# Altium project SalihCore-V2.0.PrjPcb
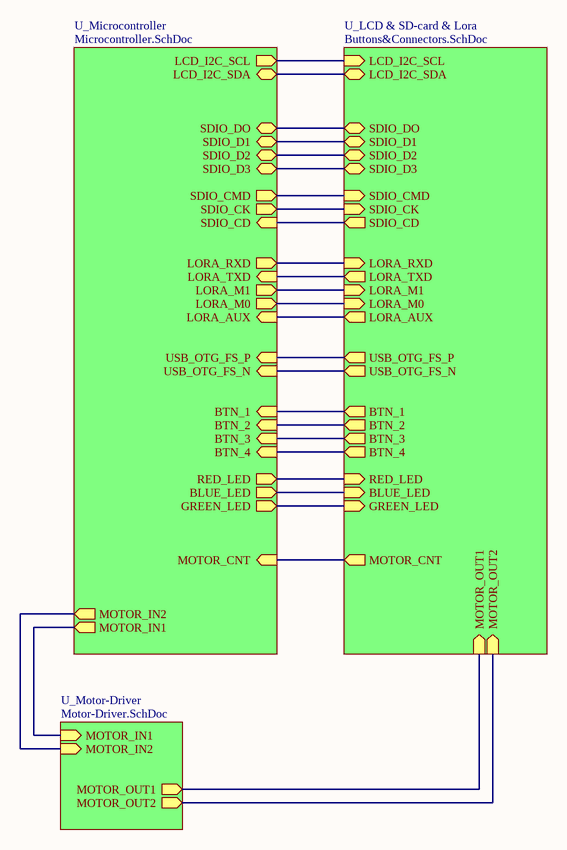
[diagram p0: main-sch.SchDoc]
6 sheets, 107 parts. Net scope: hierarchical (ports join the sheet entries above them; power ports are global).
Board file: SalihCore-V2.0-PCB.PcbDoc
Sheets:
  main-sch.SchDoc
    U_Microcontroller = Microcontroller.SchDoc
    U_LCD & SD-card & Lora = Buttons&Connectors.SchDoc
    U_Motor-Driver = Motor-Driver.SchDoc
  SMPS.SchDoc
  TP4056.SchDoc

## Sheet main-sch.SchDoc
size A; SheetNumber: 1; SheetTotal: 6

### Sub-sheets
U_LCD & SD-card & Lora = Buttons&Connectors.SchDoc: LCD_I2C_SCL (in), LCD_I2C_SDA (bidir), SDIO_DO (bidir), SDIO_D1 (bidir), SDIO_D2 (bidir), SDIO_D3 (bidir), SDIO_CMD (in), SDIO_CK (in), SDIO_CD (out), LORA_RXD (in), LORA_TXD (out), LORA_M1 (in), LORA_M0 (in), LORA_AUX (out), BTN_1 (out), BTN_2 (out), BTN_3 (out), BTN_4 (out), MOTOR_OUT1 (in), MOTOR_OUT2 (in), MOTOR_CNT (out), RED_LED (in), BLUE_LED (in), GREEN_LED (in), USB_OTG_FS_P (out), USB_OTG_FS_N (out)
U_Microcontroller = Microcontroller.SchDoc: SDIO_DO (bidir), SDIO_D1 (bidir), SDIO_D2 (bidir), SDIO_D3 (bidir), SDIO_CK (out), SDIO_CMD (out), LCD_I2C_SCL (out), LCD_I2C_SDA (bidir), SDIO_CD (in), LORA_RXD (out), LORA_TXD (in), LORA_M1 (out), LORA_M0 (out), LORA_AUX (in), MOTOR_IN1 (out), MOTOR_IN2 (out), BTN_1 (in), BTN_2 (in), BTN_3 (in), BTN_4 (in), MOTOR_CNT (in), RED_LED (out), BLUE_LED (out), GREEN_LED (out), USB_OTG_FS_P (in), USB_OTG_FS_N (in)
U_Motor-Driver = Motor-Driver.SchDoc: MOTOR_IN1 (in), MOTOR_IN2 (in), MOTOR_OUT1 (out), MOTOR_OUT2 (out)

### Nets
BLUE_LED: sheet U_Microcontroller/BLUE_LED, sheet U_LCD & SD-card & Lora/BLUE_LED
BTN_1: sheet U_Microcontroller/BTN_1, sheet U_LCD & SD-card & Lora/BTN_1
BTN_2: sheet U_Microcontroller/BTN_2, sheet U_LCD & SD-card & Lora/BTN_2
BTN_3: sheet U_Microcontroller/BTN_3, sheet U_LCD & SD-card & Lora/BTN_3
BTN_4: sheet U_Microcontroller/BTN_4, sheet U_LCD & SD-card & Lora/BTN_4
GREEN_LED: sheet U_Microcontroller/GREEN_LED, sheet U_LCD & SD-card & Lora/GREEN_LED
LCD_I2C_SCL: sheet U_Microcontroller/LCD_I2C_SCL, sheet U_LCD & SD-card & Lora/LCD_I2C_SCL
LCD_I2C_SDA: sheet U_Microcontroller/LCD_I2C_SDA, sheet U_LCD & SD-card & Lora/LCD_I2C_SDA
LORA_AUX: sheet U_Microcontroller/LORA_AUX, sheet U_LCD & SD-card & Lora/LORA_AUX
LORA_M0: sheet U_Microcontroller/LORA_M0, sheet U_LCD & SD-card & Lora/LORA_M0
LORA_M1: sheet U_Microcontroller/LORA_M1, sheet U_LCD & SD-card & Lora/LORA_M1
LORA_RXD: sheet U_Microcontroller/LORA_RXD, sheet U_LCD & SD-card & Lora/LORA_RXD
LORA_TXD: sheet U_Microcontroller/LORA_TXD, sheet U_LCD & SD-card & Lora/LORA_TXD
MOTOR_CNT: sheet U_Microcontroller/MOTOR_CNT, sheet U_LCD & SD-card & Lora/MOTOR_CNT
MOTOR_IN1: sheet U_Microcontroller/MOTOR_IN1, sheet U_Motor-Driver/MOTOR_IN1
MOTOR_IN2: sheet U_Microcontroller/MOTOR_IN2, sheet U_Motor-Driver/MOTOR_IN2
MOTOR_OUT1: sheet U_LCD & SD-card & Lora/MOTOR_OUT1, sheet U_Motor-Driver/MOTOR_OUT1
MOTOR_OUT2: sheet U_LCD & SD-card & Lora/MOTOR_OUT2, sheet U_Motor-Driver/MOTOR_OUT2
RED_LED: sheet U_Microcontroller/RED_LED, sheet U_LCD & SD-card & Lora/RED_LED
SDIO_CD: sheet U_Microcontroller/SDIO_CD, sheet U_LCD & SD-card & Lora/SDIO_CD
SDIO_CK: sheet U_Microcontroller/SDIO_CK, sheet U_LCD & SD-card & Lora/SDIO_CK
SDIO_CMD: sheet U_Microcontroller/SDIO_CMD, sheet U_LCD & SD-card & Lora/SDIO_CMD
SDIO_D1: sheet U_Microcontroller/SDIO_D1, sheet U_LCD & SD-card & Lora/SDIO_D1
SDIO_D2: sheet U_Microcontroller/SDIO_D2, sheet U_LCD & SD-card & Lora/SDIO_D2
SDIO_D3: sheet U_Microcontroller/SDIO_D3, sheet U_LCD & SD-card & Lora/SDIO_D3
SDIO_DO: sheet U_Microcontroller/SDIO_DO, sheet U_LCD & SD-card & Lora/SDIO_DO
USB_OTG_FS_N: sheet U_Microcontroller/USB_OTG_FS_N, sheet U_LCD & SD-card & Lora/USB_OTG_FS_N
USB_OTG_FS_P: sheet U_Microcontroller/USB_OTG_FS_P, sheet U_LCD & SD-card & Lora/USB_OTG_FS_P

## Sheet Microcontroller.SchDoc
size C; SheetNumber: 2; SheetTotal: 6
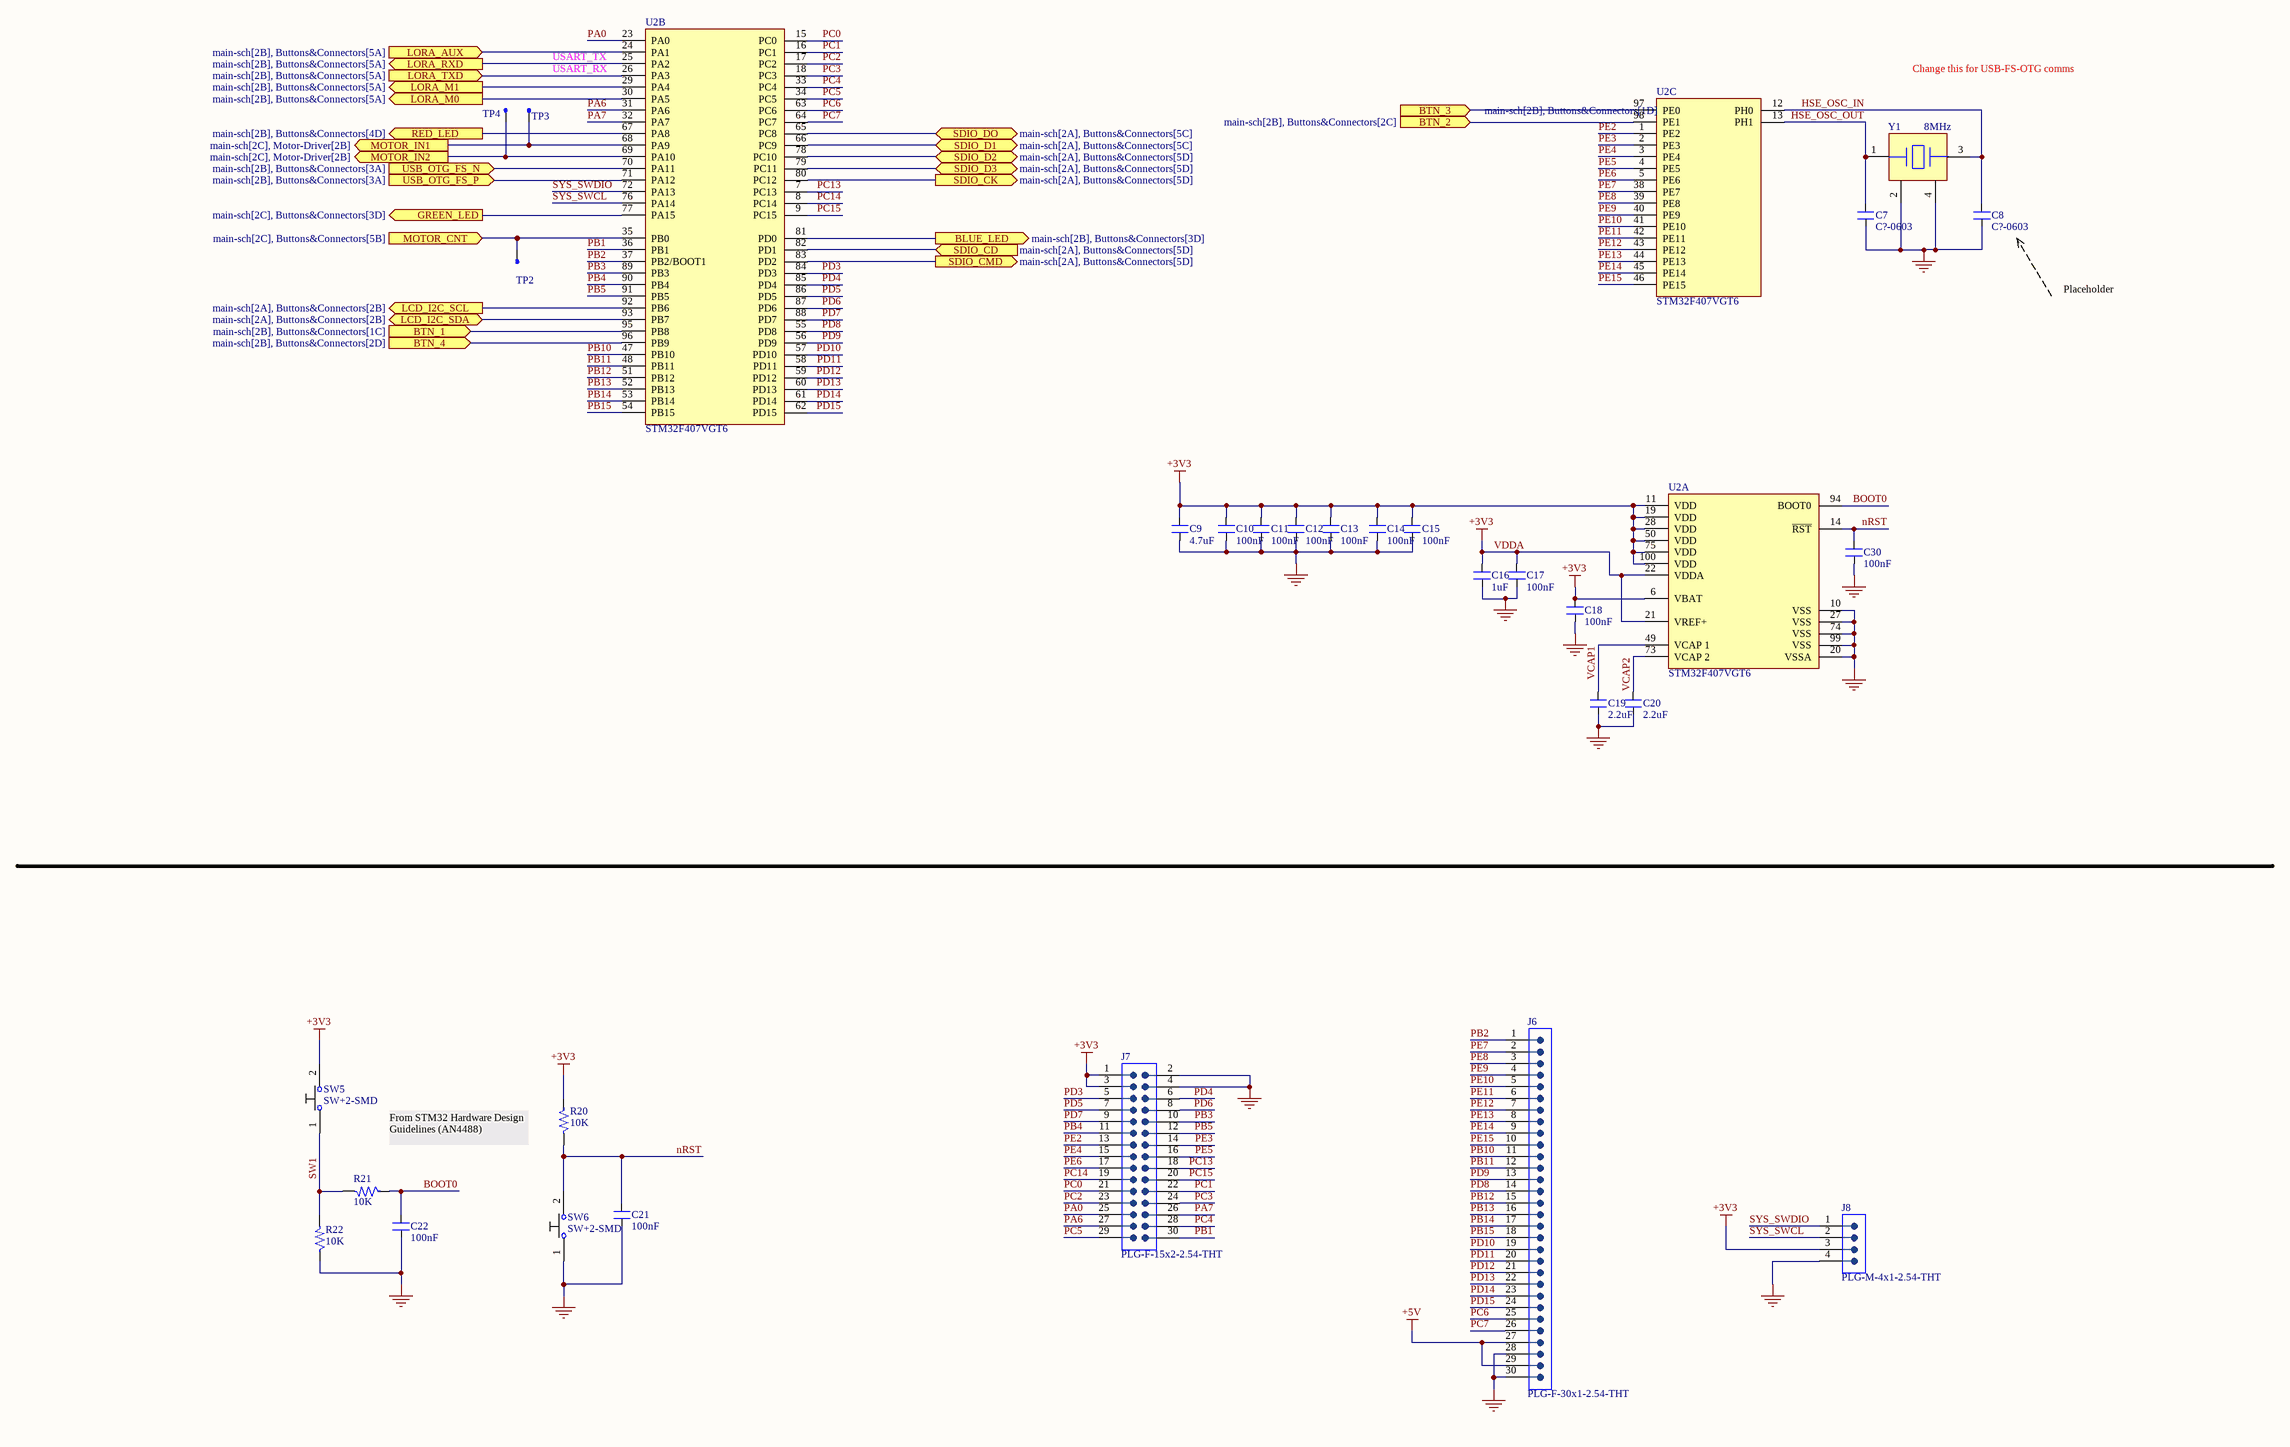
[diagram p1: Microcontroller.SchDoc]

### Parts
(Parts that share a designator on the sheet are numbered #1, #2 ... from top to bottom, then left to right.)
C7  C?-0603  [CAP-0603]
C8  C?-0603  [CAP-0603]
C9  4.7uF  [CAP-0603]
C10  100nF  [CAP-0603]
C11  100nF  [CAP-0603]
C12  100nF  [CAP-0603]
C13  100nF  [CAP-0603]
C14  100nF  [CAP-0603]
C15  100nF  [CAP-0603]
C16  1uF  [CAP-0603]
C17  100nF  [CAP-0603]
C18  100nF  [CAP-0603]
C19  2.2uF  [CAP-0603]
C20  2.2uF  [CAP-0603]
C21  100nF  [CAP-0603]
C22  100nF  [CAP-0603]
C30  100nF  [CAP-0603]
J6#1  PLG-F-30x1-2.54-THT  [PLG-F-30x1-2.54-THT]
J7  PLG-F-15x2-2.54-THT  [PLG-F-15x2-2.54-THT]
J8  PLG-M-4x1-2.54-THT  [PLG-M-4x1-2.54-THT]
R20  10K  [RES-0603]
R21  10K  [RES-0603]
R22  10K  [RES-0603]
SW5  SW+2-SMD  [SW+2-SMD]
SW6  SW+2-SMD  [SW+2-SMD]
TP2  Test-Point  [Test Point]  (value not drawn)
TP3  Test-Point  [Test Point]  (value not drawn)
TP4  Test-Point  [Test Point]  (value not drawn)
U2  STM32F407VGT6  [LQFP-100-14x14]  (parts A,B,C of 3)
Y1  8MHz  [XTAL-TX32258M4LBDE2T-HM]

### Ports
BLUE_LED (out, see main-sch[2B], Buttons&Connectors[3D]), BTN_1 (in, see main-sch[2B], Buttons&Connectors[1C]), BTN_2 (in, see main-sch[2B], Buttons&Connectors[2C]), BTN_3 (in, see main-sch[2B], Buttons&Connectors[1D]), BTN_4 (in, see main-sch[2B], Buttons&Connectors[2D]), GREEN_LED (out, see main-sch[2C], Buttons&Connectors[3D]), LCD_I2C_SCL (out, see main-sch[2A], Buttons&Connectors[2B]), LCD_I2C_SDA (bidir, see main-sch[2A], Buttons&Connectors[2B]), LORA_AUX (in, see main-sch[2B], Buttons&Connectors[5A]), LORA_M0 (out, see main-sch[2B], Buttons&Connectors[5A]), LORA_M1 (out, see main-sch[2B], Buttons&Connectors[5A]), LORA_RXD (out, see main-sch[2B], Buttons&Connectors[5A]), LORA_TXD (in, see main-sch[2B], Buttons&Connectors[5A]), MOTOR_CNT (in, see main-sch[2C], Buttons&Connectors[5B]), MOTOR_IN1 (out, see main-sch[2C], Motor-Driver[2B]), MOTOR_IN2 (out, see main-sch[2C], Motor-Driver[2B]), RED_LED (out, see main-sch[2B], Buttons&Connectors[4D]), SDIO_CD (in, see main-sch[2A], Buttons&Connectors[5D]), SDIO_CK (out, see main-sch[2A], Buttons&Connectors[5D]), SDIO_CMD (out, see main-sch[2A], Buttons&Connectors[5D]), SDIO_D1 (bidir, see main-sch[2A], Buttons&Connectors[5C]), SDIO_D2 (bidir, see main-sch[2A], Buttons&Connectors[5D]), SDIO_D3 (bidir, see main-sch[2A], Buttons&Connectors[5D]), SDIO_DO (bidir, see main-sch[2A], Buttons&Connectors[5C]), USB_OTG_FS_N (in, see main-sch[2B], Buttons&Connectors[3A]), USB_OTG_FS_P (in, see main-sch[2B], Buttons&Connectors[3A])

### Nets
+5V: J6#1.27 J6#1.29
GND: C7.1 C8.1 C9.1 C10.1 C11.1 C12.1 C13.1 C14.1 C15.1 C16.1 C17.1 C18.1 C19.1 C20.1 C21.1 C22.1 C30.1 J6#1.28 J6#1.30 J7.2 J7.4 J8.4 R22.1 SW6.1 U2.10(VSS) U2.20(VSSA) U2.27(VSS) U2.74(VSS) U2.99(VSS) Y1.2(GND) Y1.4(GND)
VDDA: C9.2 C10.2 C11.2 C12.2 C13.2 C14.2 C15.2 C16.2 C17.2 C18.2 J7.1 J7.3 J8.3 R20.1 SW5.2 U2.6(VBAT) U2.11(VDD) U2.19(VDD) U2.21(VREF+) U2.22(VDDA) U2.28(VDD) U2.50(VDD) U2.75(VDD) U2.100(VDD)  [also labelled +3V3]
BLUE_LED: U2.81(PD0) ; port BLUE_LED
BOOT0: C22.2 R21.1 U2.94(BOOT0)
BTN_1: U2.95(PB8) ; port BTN_1
BTN_2: U2.98(PE1) ; port BTN_2
BTN_3: U2.97(PE0) ; port BTN_3
BTN_4: U2.96(PB9) ; port BTN_4
GREEN_LED: U2.77(PA15) ; port GREEN_LED
HSE_OSC_IN: C8.2 U2.12(PH0) Y1.3
HSE_OSC_OUT: C7.2 U2.13(PH1) Y1.1
LCD_I2C_SCL: U2.92(PB6) ; port LCD_I2C_SCL
LCD_I2C_SDA: U2.93(PB7) ; port LCD_I2C_SDA
LORA_AUX: U2.24(PA1) ; port LORA_AUX
LORA_M0: U2.30(PA5) ; port LORA_M0
LORA_M1: U2.29(PA4) ; port LORA_M1
LORA_RXD: U2.25(PA2) ; port LORA_RXD
LORA_TXD: U2.26(PA3) ; port LORA_TXD
MOTOR_CNT: TP2.1 U2.35(PB0) ; port MOTOR_CNT
MOTOR_IN1: TP3.1 U2.68(PA9) ; port MOTOR_IN1
MOTOR_IN2: TP4.1 U2.69(PA10) ; port MOTOR_IN2
nRST: C21.2 C30.2 R20.2 SW6.2 U2.14(~{RST})
PA0: J7.25 U2.23(PA0)
PA6: J7.27 U2.31(PA6)
PA7: J7.26 U2.32(PA7)
PB1: J7.30 U2.36(PB1)
PB2: J6#1.1 U2.37(PB2/BOOT1)
PB3: J7.10 U2.89(PB3)
PB4: J7.11 U2.90(PB4)
PB5: J7.12 U2.91(PB5)
PB10: J6#1.11 U2.47(PB10)
PB11: J6#1.12 U2.48(PB11)
PB12: J6#1.15 U2.51(PB12)
PB13: J6#1.16 U2.52(PB13)
PB14: J6#1.17 U2.53(PB14)
PB15: J6#1.18 U2.54(PB15)
PC0: J7.21 U2.15(PC0)
PC1: J7.22 U2.16(PC1)
PC2: J7.23 U2.17(PC2)
PC3: J7.24 U2.18(PC3)
PC4: J7.28 U2.33(PC4)
PC5: J7.29 U2.34(PC5)
PC6: J6#1.25 U2.63(PC6)
PC7: J6#1.26 U2.64(PC7)
PC13: J7.18 U2.7(PC13)
PC14: J7.19 U2.8(PC14)
PC15: J7.20 U2.9(PC15)
PD3: J7.5 U2.84(PD3)
PD4: J7.6 U2.85(PD4)
PD5: J7.7 U2.86(PD5)
PD6: J7.8 U2.87(PD6)
PD7: J7.9 U2.88(PD7)
PD8: J6#1.14 U2.55(PD8)
PD9: J6#1.13 U2.56(PD9)
PD10: J6#1.19 U2.57(PD10)
PD11: J6#1.20 U2.58(PD11)
PD12: J6#1.21 U2.59(PD12)
PD13: J6#1.22 U2.60(PD13)
PD14: J6#1.23 U2.61(PD14)
PD15: J6#1.24 U2.62(PD15)
PE2: J7.13 U2.1(PE2)
PE3: J7.14 U2.2(PE3)
PE4: J7.15 U2.3(PE4)
PE5: J7.16 U2.4(PE5)
PE6: J7.17 U2.5(PE6)
PE7: J6#1.2 U2.38(PE7)
PE8: J6#1.3 U2.39(PE8)
PE9: J6#1.4 U2.40(PE9)
PE10: J6#1.5 U2.41(PE10)
PE11: J6#1.6 U2.42(PE11)
PE12: J6#1.7 U2.43(PE12)
PE13: J6#1.8 U2.44(PE13)
PE14: J6#1.9 U2.45(PE14)
PE15: J6#1.10 U2.46(PE15)
RED_LED: U2.67(PA8) ; port RED_LED
SDIO_CD: U2.82(PD1) ; port SDIO_CD
SDIO_CK: U2.80(PC12) ; port SDIO_CK
SDIO_CMD: U2.83(PD2) ; port SDIO_CMD
SDIO_D1: U2.66(PC9) ; port SDIO_D1
SDIO_D2: U2.78(PC10) ; port SDIO_D2
SDIO_D3: U2.79(PC11) ; port SDIO_D3
SDIO_DO: U2.65(PC8) ; port SDIO_DO
SW1: R21.2 R22.2 SW5.1
SYS_SWCL: J8.2 U2.76(PA14)
SYS_SWDIO: J8.1 U2.72(PA13)
USB_OTG_FS_N: U2.70(PA11) ; port USB_OTG_FS_N
USB_OTG_FS_P: U2.71(PA12) ; port USB_OTG_FS_P
VCAP1: C19.2 U2.49(VCAP_1)
VCAP2: C20.2 U2.73(VCAP_2)

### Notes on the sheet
- USART_TX
- USART_RX
- Change this for USB-FS-OTG comms
- Placeholder
- From STM32 Hardware Design Guidelines (AN4488)

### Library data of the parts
C7 C8 = 2: part number: CL10B104KA8NNNC; manufacturer: Samsung Electro-Mechanics; ID: 2
C9 = 5: 35V 4.7uF X5R ±10% 0603 Multilayer Ceramic Capacitors MLCC - SMD/SMT ROHS; part number: GRM188R6YA475KE15D; manufacturer: murata; ID: 5
C10-C15 C17 C18 C21 C22 C30 = 2: 25V 100nF X7R ±10% 0603; part number: CL10B104KA8NNNC; manufacturer: Samsung Electro-Mechanics; ID: 2
C16 = 3: 25V 1uF X7R ±10% 0603; part number: CL10B105KA8NNNC; manufacturer: samsung; ID: 3
C19 C20 = 4: 16V 2.2uF X5R ±10% 0603 Multilayer Ceramic Capacitors MLCC - SMD/SMT; part number: C0603C225K4PAC7867; manufacturer: KEMET; ID: 4
J6#1 = 5: 30 rows, 1 column, female,2.54mm, tht pin header; ID: 5
J7 = 2: 15 rows, 2 column, female,2.54mm, tht pin header; ID: 2
J8 = 1: 4 rows, 1 column, 2.54mm, tht pin header; ID: 1
R20-R22 = 1: 250mW Thick Film Resistors 150V ±100ppm/℃ ±1% 10kΩ 0603 Chip Resistor - Surface Mount ROHS; part number: ESR03EZPF1002; manufacturer: ROHM Semicon; ID: 1
SW5 SW6 = SW+2-SMD: pkg: SMD; distr: digikey; dpn: CKN12217-1-ND
U2 = 1: High-performance base series ARM Cortex-M4 MCU with DSP and FPU, featuring 1 MB Flash, 168 MHz CPU, ART accelerator, Ethernet, and FSMC; manufacturer: STMicroelectronics; ID: 1
Y1 = XTAL_8MHz-TX32258M4LBDE2T: mfr: Yajingxin; pkg: SMD3225-4P; distr: lcsc; dpn: C5310727

## Sheet Buttons&Connectors.SchDoc
size C; SheetNumber: 3; SheetTotal: 6
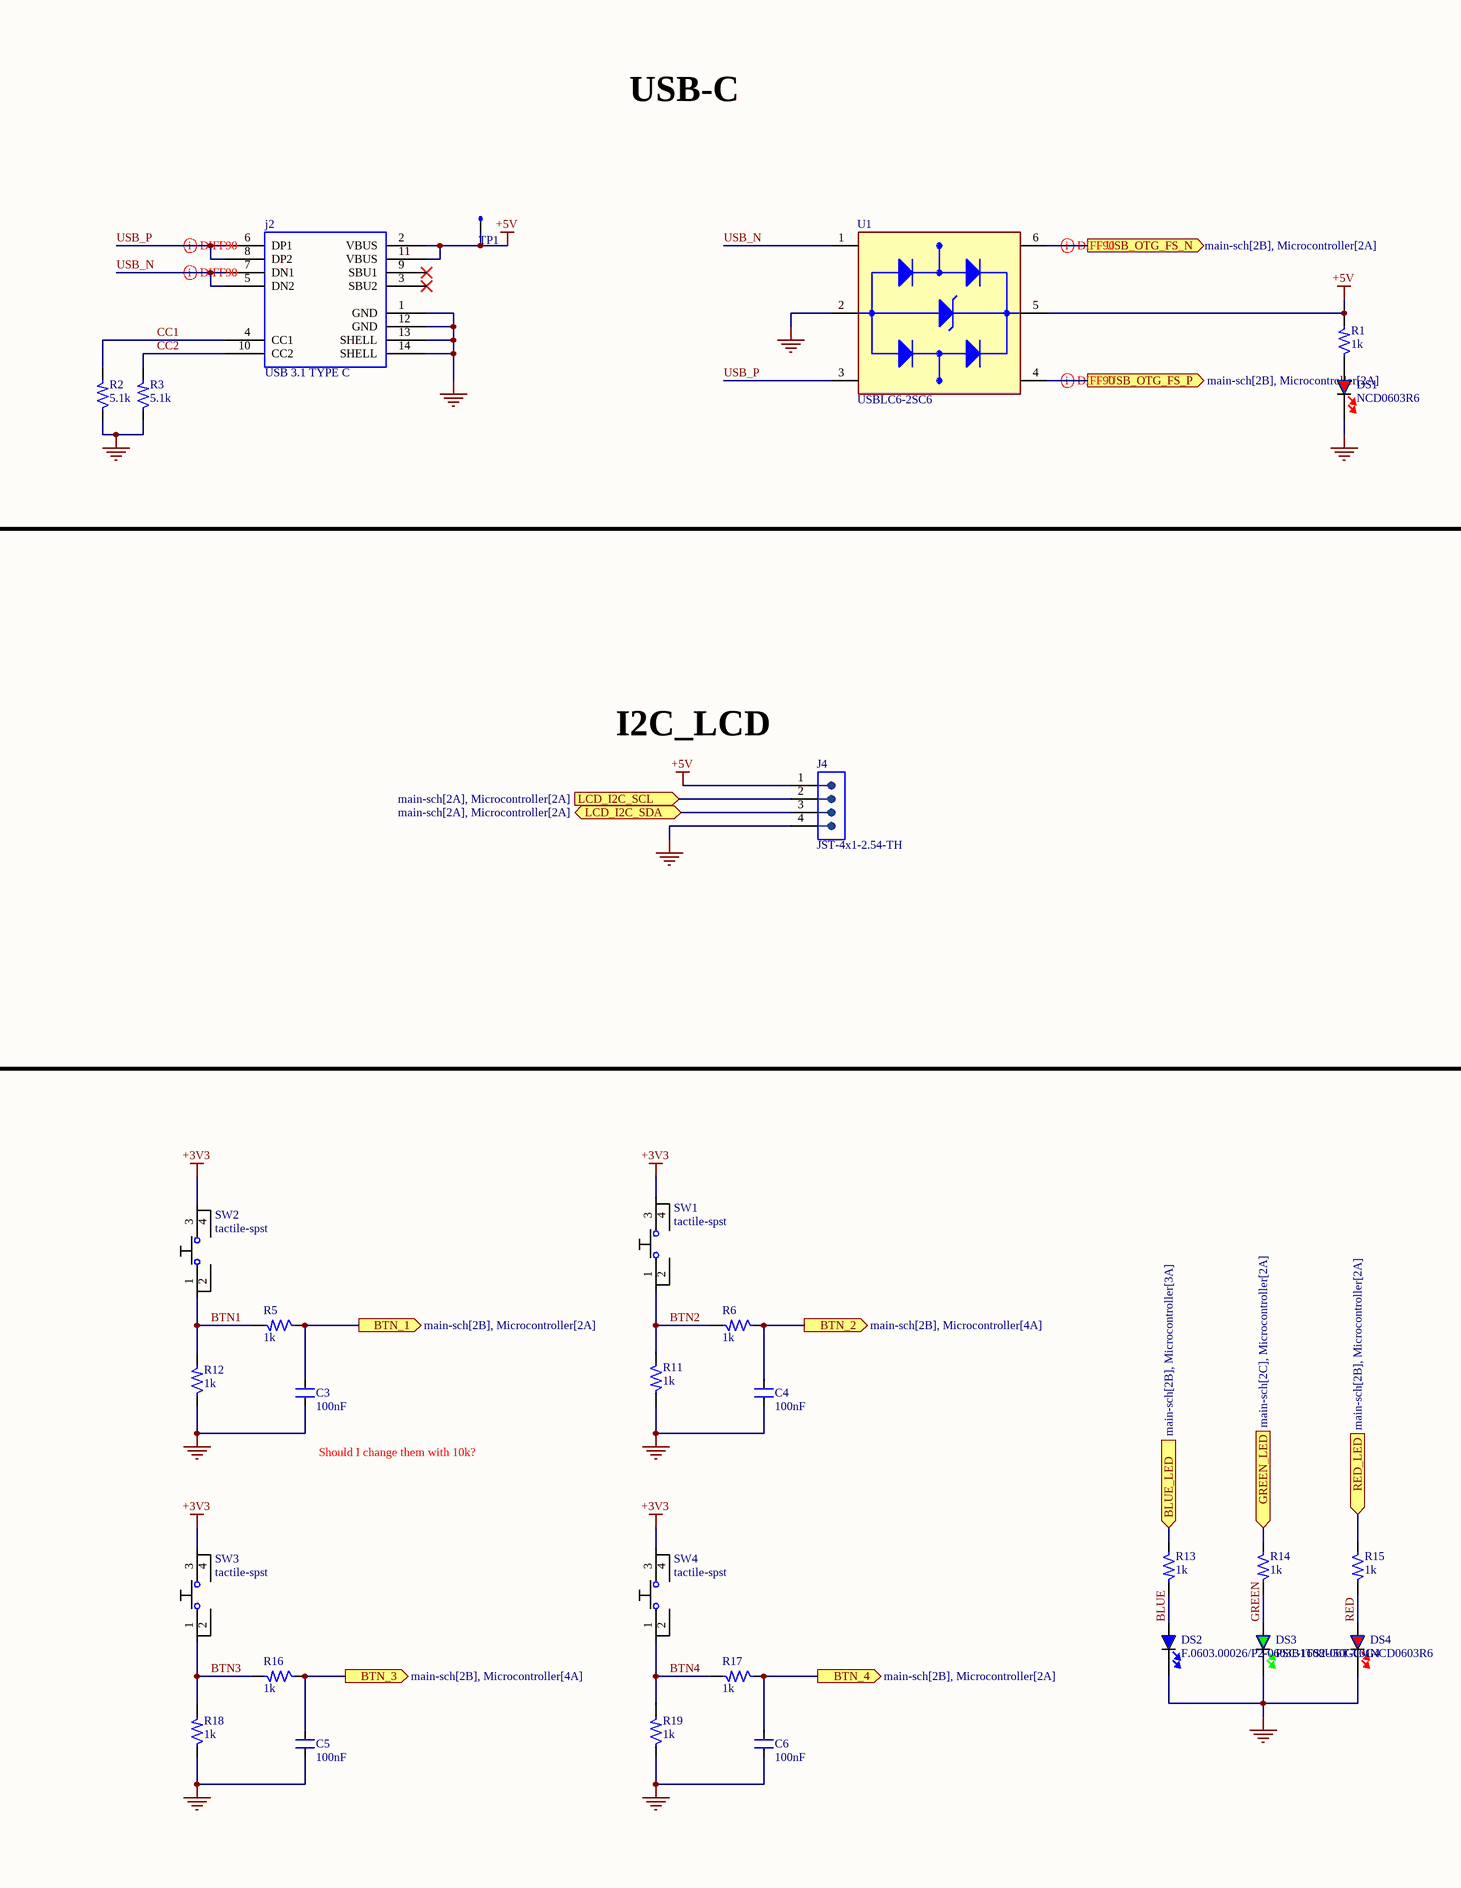
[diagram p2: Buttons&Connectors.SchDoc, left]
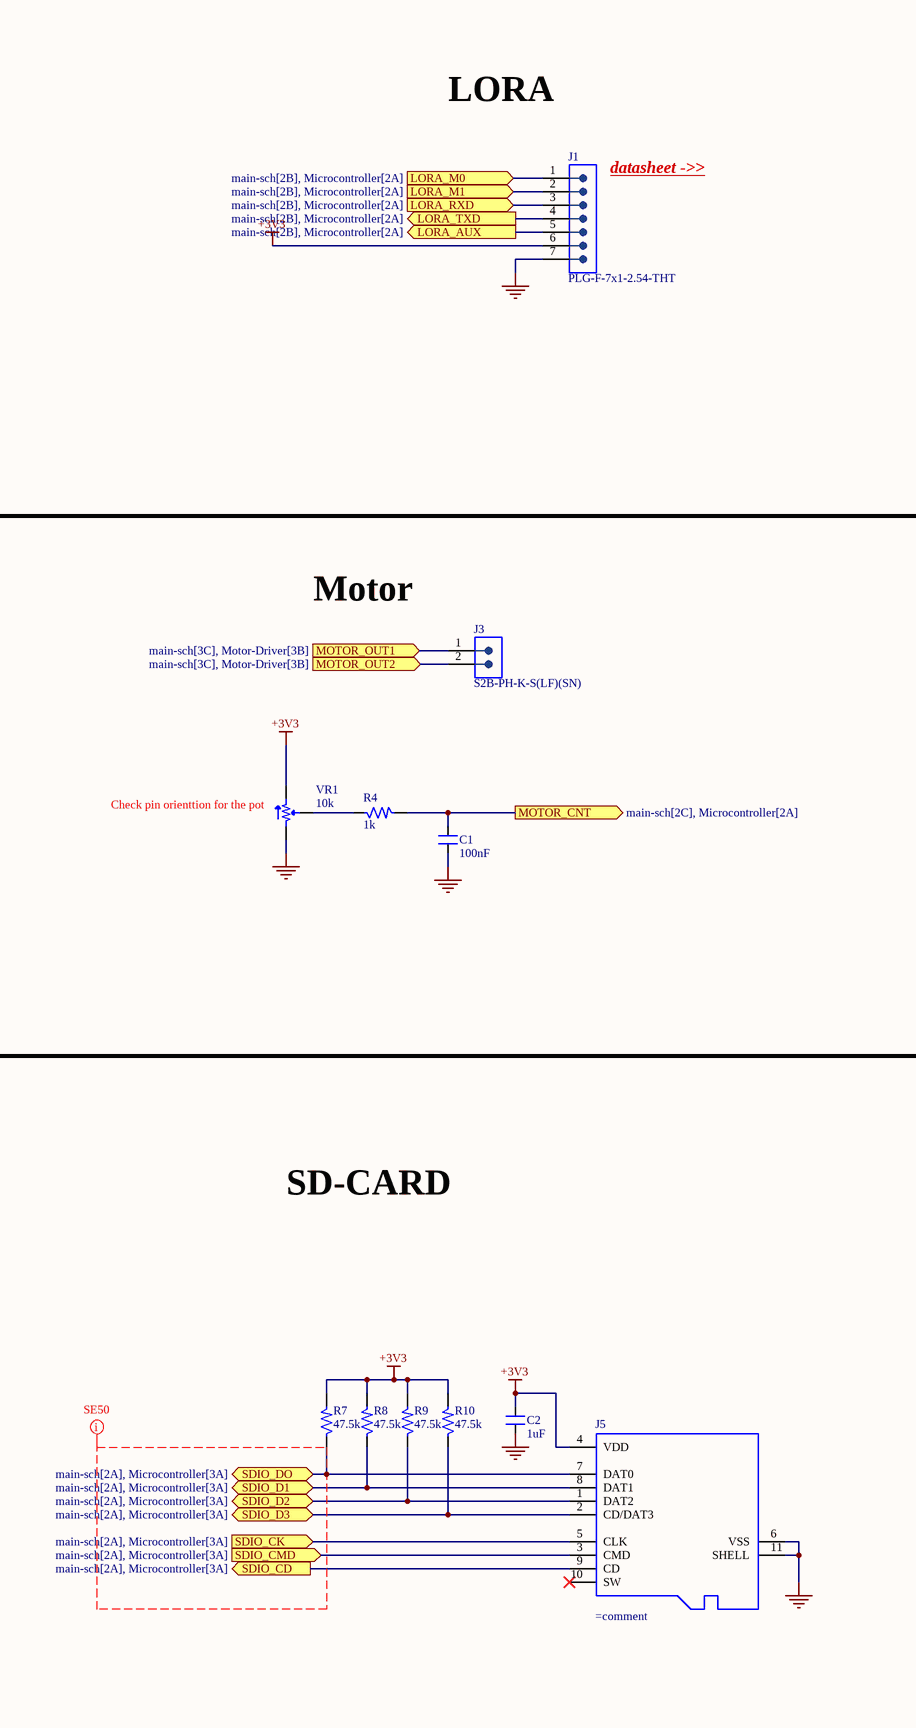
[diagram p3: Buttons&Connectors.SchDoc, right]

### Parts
C1  100nF  [CAP-0603]
C2  1uF  [CAP-0603]
C3  100nF  [CAP-0603]
C4  100nF  [CAP-0603]
C5  100nF  [CAP-0603]
C6  100nF  [CAP-0603]
DS1  NCD0603R6  [LED_0603]
DS2  F.0603.00026/P2-0603B1TS2-06T-001  [LED_0603]
DS3  PSC-1608U50GC-G4  [LED_0603]
DS4  NCD0603R6  [LED_0603]
J1  PLG-F-7x1-2.54-THT  [PLG-F-7x1-2.54-THT]
j2  USB 3.1 TYPE C  [USB3.1-TYPEC-SHOU HAN]
J3  S2B-PH-K-S(LF)(SN)  [S2B-PH-K-S(LF)(SN)]
J4  JST-4x1-2.54-TH  [JST-4x1-2.00-TH]
J5  (no value)  [112I-TA01]
R1  1k  [RES-0603]
R2  5.1k  [RES-0603]
R3  5.1k  [RES-0603]
R4  1k  [RES-0603]
R5  1k  [RES-0603]
R6  1k  [RES-0603]
R7  47.5k  [RES-0603]
R8  47.5k  [RES-0603]
R9  47.5k  [RES-0603]
R10  47.5k  [RES-0603]
R11  1k  [RES-0603]
R12  1k  [RES-0603]
R13  1k  [RES-0603]
R14  1k  [RES-0603]
R15  1k  [RES-0603]
R16  1k  [RES-0603]
R17  1k  [RES-0603]
R18  1k  [RES-0603]
R19  1k  [RES-0603]
SW1  tactile-spst  [Tact-switch-12x12]
SW2  tactile-spst  [Tact-switch-12x12]
SW3  tactile-spst  [Tact-switch-12x12]
SW4  tactile-spst  [Tact-switch-12x12]
TP1  Test-Point  [Test Point]  (value not drawn)
U1  USBLC6-2SC6  [SOT23-6]
VR1  10k  [RES-TRIMPOT]

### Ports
BLUE_LED (in, see main-sch[2B], Microcontroller[3A]), BTN_1 (out, see main-sch[2B], Microcontroller[2A]), BTN_2 (out, see main-sch[2B], Microcontroller[4A]), BTN_3 (out, see main-sch[2B], Microcontroller[4A]), BTN_4 (out, see main-sch[2B], Microcontroller[2A]), GREEN_LED (in, see main-sch[2C], Microcontroller[2A]), LCD_I2C_SCL (in, see main-sch[2A], Microcontroller[2A]), LCD_I2C_SDA (bidir, see main-sch[2A], Microcontroller[2A]), LORA_AUX (out, see main-sch[2B], Microcontroller[2A]), LORA_M0 (in, see main-sch[2B], Microcontroller[2A]), LORA_M1 (in, see main-sch[2B], Microcontroller[2A]), LORA_RXD (in, see main-sch[2B], Microcontroller[2A]), LORA_TXD (out, see main-sch[2B], Microcontroller[2A]), MOTOR_CNT (out, see main-sch[2C], Microcontroller[2A]), MOTOR_OUT1 (in, see main-sch[3C], Motor-Driver[3B]), MOTOR_OUT2 (in, see main-sch[3C], Motor-Driver[3B]), RED_LED (in, see main-sch[2B], Microcontroller[2A]), SDIO_CD (out, see main-sch[2A], Microcontroller[3A]), SDIO_CK (in, see main-sch[2A], Microcontroller[3A]), SDIO_CMD (in, see main-sch[2A], Microcontroller[3A]), SDIO_D1 (bidir, see main-sch[2A], Microcontroller[3A]), SDIO_D2 (bidir, see main-sch[2A], Microcontroller[3A]), SDIO_D3 (bidir, see main-sch[2A], Microcontroller[3A]), SDIO_DO (bidir, see main-sch[2A], Microcontroller[3A]), USB_OTG_FS_N (out, see main-sch[2B], Microcontroller[2A]), USB_OTG_FS_P (out, see main-sch[2B], Microcontroller[2A])

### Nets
+3V3: C2.2 J1.6 J5.4(VDD) R7.2 R8.2 R9.2 R10.2 SW1.3 SW2.3 SW3.3 SW4.3 VR1.3  [project net VDDA]
+5V: j2.2(VBUS) j2.11(VBUS) J4.1 R1.2 TP1.1 U1.5(VBUS)
GND: C1.1 C2.1 C3.1 C4.1 C5.1 C6.1 DS1.K DS2.K DS3.K DS4.K J1.7 j2.1(GND) j2.12(GND) j2.13(SHELL) j2.14(SHELL) J4.4 J5.6(VSS) J5.11(SHELL) R2.1 R3.1 R11.2 R12.1 R18.1 R19.1 U1.2(GND) VR1.2
BLUE: DS2.A R13.2
BLUE_LED: R13.1 ; port BLUE_LED
BTN1: R5.2 R12.2 SW2.1
BTN2: R6.2 R11.1 SW1.1
BTN3: R16.2 R18.2 SW3.1
BTN4: R17.2 R19.2 SW4.1
BTN_1: C3.2 R5.1 ; port BTN_1
BTN_2: C4.2 R6.1 ; port BTN_2
BTN_3: C5.2 R16.1 ; port BTN_3
BTN_4: C6.2 R17.1 ; port BTN_4
CC1: j2.4(CC1) R2.2
CC2: j2.10(CC2) R3.2
GREEN: DS3.A R14.2
GREEN_LED: R14.1 ; port GREEN_LED
LCD_I2C_SCL: J4.2 ; port LCD_I2C_SCL
LCD_I2C_SDA: J4.3 ; port LCD_I2C_SDA
LORA_AUX: J1.5 ; port LORA_AUX
LORA_M0: J1.1 ; port LORA_M0
LORA_M1: J1.2 ; port LORA_M1
LORA_RXD: J1.3 ; port LORA_RXD
LORA_TXD: J1.4 ; port LORA_TXD
MOTOR_CNT: C1.2 R4.2 ; port MOTOR_CNT
MOTOR_OUT1: J3.1 ; port MOTOR_OUT1
MOTOR_OUT2: J3.2 ; port MOTOR_OUT2
RED: DS4.A R15.2
RED_LED: R15.1 ; port RED_LED
SDIO_CD: J5.9(CD) ; port SDIO_CD
SDIO_CK: J5.5(CLK) ; port SDIO_CK
SDIO_CMD: J5.3(CMD) ; port SDIO_CMD
SDIO_D1: J5.8(DAT1) R8.1 ; port SDIO_D1
SDIO_D2: J5.1(DAT2) R9.1 ; port SDIO_D2
SDIO_D3: J5.2(CD/DAT3) R10.1 ; port SDIO_D3
SDIO_DO: J5.7(DAT0) R7.1 ; port SDIO_DO
USB_N: j2.5(DN2) j2.7(DN1) U1.1(I/O1_IN)
USB_OTG_FS_N: U1.6(I/O1_OUT) ; port USB_OTG_FS_N
USB_OTG_FS_P: U1.4(I/O2_OUT) ; port USB_OTG_FS_P
USB_P: j2.6(DP1) j2.8(DP2) U1.3(I/O2_IN)
NetDS1_A: DS1.A R1.1
NetR4_1: R4.1 VR1.1

Not connected (* = marked no-connect by the designer): j2 3(SBU2)* 9(SBU1)*; J5 10(SW)*; SW1 2 4; SW2 2 4; SW3 2 4; SW4 2 4

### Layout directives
differential pair; differential pair class DIFF90; net class DIFF-45-SE: USB_N, USB_OTG_FS_N, USB_OTG_FS_P, USB_P
net class SE50: (no net found under the mark)

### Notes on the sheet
- USB-C
- LORA
- (near J1) datasheet ->> <C:\UNIVERSITY\4.YIL\Bitirme Projesi\Datasheets\E22-900T22D_UserManual.pdf>
- Motor
- I2C_LCD
- (near VR1) Check pin orienttion for the pot
- SD-CARD
- (near C3) Should I change them with 10k?

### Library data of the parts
C1 C3-C6 = 2: as C10 on sheet Microcontroller
C2 = 3: as C16 on sheet Microcontroller
DS1 DS4 = LED_Red-2V-25mA-0603: 25mA Colorless Transparent Lens 30mcd~80mcd 620nm~630nm -30℃~+85℃ Red 140° 65mW 1.6V~2.4V 0603 LED Indication - Discrete ROHS; pkg: 0603; distr: LCSC; dpn: C7429910
DS2 = LED_Blue-2.9V-30mA-0603: -40℃~+85℃ Blue 120° 0603 LED Indication - Discrete ROHS; pkg: 0603; distr: LCSC; dpn: C7496819
DS3 = LED_Green-3V-10mA-0603: Green 0603 LED Indication; pkg: 0603; distr: LCSC; dpn: C22371298
J1 = 3: 7 rows, 1 column, female,2.54mm, tht pin header; ID: 3
j2 = USB3.1_TYPEC_SMD: 5A USB 3.1 1 Horizontal attachment 16P Female -25℃~+85℃ Type-C SMD USB Connectors ROHS; mfr.: SHOU HAN; mpn: TYPE-C 16PIN 2MD(073); distr.: LCSC; dpn: C2765186
J5 = 112I-TA01
R1 R4-R6 R11-R19 = 16: 250mW Thick Film Resistors 75V ±100ppm/℃ ±5% 1.5kΩ 0603 Chip Resistor - Surface Mount ROHS; part number: AS03W4J0152T5E; manufacturer: UNI-ROYAL; ID: 16
R2 R3 = 32: RES.(1608) 0603 5.1K Ohms 1% 1/10W-S 100PPM; ID: 32; Field6: 0
R7-R10 = 22: 47.5K-100mW-±1%-0603; ID: 22
SW1-SW4 = tactile-spst: pkg: SMD
U1 = USBLC6-2SC6: 17V Clamp 5A (8/20Âµs) Ipp Tvs Diode Surface Mount SOT-23-6; pkg: SMD
VR1 = RES-V-10K-250mW-THT

## Sheet Motor-Driver.SchDoc
size A; SheetNumber: 4; SheetTotal: 6
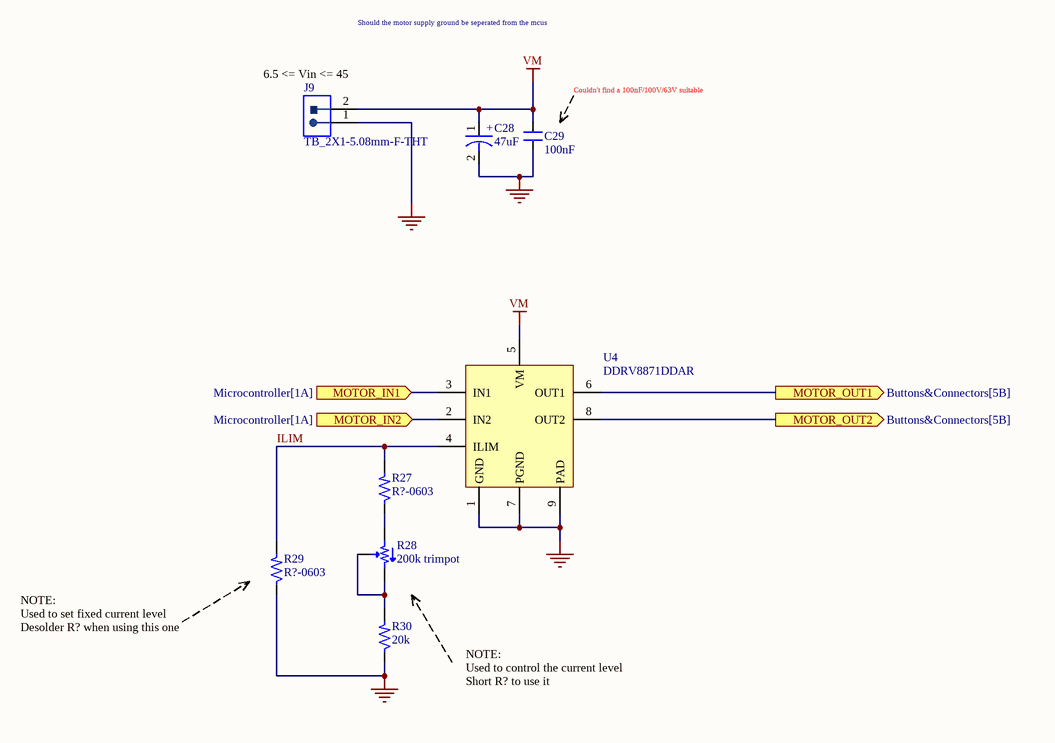
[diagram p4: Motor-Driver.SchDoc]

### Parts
(Parts that share a designator on the sheet are numbered #1, #2 ... from top to bottom, then left to right.)
C28#1  47uF  [radial-D6.3-H12-P3]
C29  100nF  [CAP-0603]
J9  TB_2X1-5.08mm-F-THT  [TB_2X1-5.08mm-F-THT]
R27#1  R?-0603  [RES-0603]
R28#1  200k trimpot  [POT_3386F]
R29  R?-0603  [RES-0603]
R30  20k  [RES-0603]
U4#1  DDRV8871DDAR  [8-PowerSOIC]

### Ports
MOTOR_IN1 (in, see Microcontroller[1A]), MOTOR_IN2 (in, see Microcontroller[1A]), MOTOR_OUT1 (out, see Buttons&Connectors[5B]), MOTOR_OUT2 (out, see Buttons&Connectors[5B])

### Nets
GND: C28#1.2 C29.1 J9.1 R29.1 R30.1 U4#1.1(GND) U4#1.7(PGND) U4#1.9(PAD)
VM: C28#1.1 C29.2 J9.2 U4#1.5(VM)
ILIM: R27#1.2 R29.2 U4#1.4(ILIM)
MOTOR_IN1: U4#1.3(IN1) ; port MOTOR_IN1
MOTOR_IN2: U4#1.2(IN2) ; port MOTOR_IN2
MOTOR_OUT1: U4#1.6(OUT1) ; port MOTOR_OUT1
MOTOR_OUT2: U4#1.8(OUT2) ; port MOTOR_OUT2
NetR27#1_1: R27#1.1 R28#1.2
NetR28#1_1: R28#1.1 R28#1.3 R30.2

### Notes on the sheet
- Should the motor supply ground be seperated from the mcus
- (near J9) 6.5 <= Vin <= 45
- Couldn't find a 100nF/100V/63V suitable
- NOTE:
- Used to set fixed current level
- Desolder R? when using this one
- Used to control the current level
- Short R? to use it

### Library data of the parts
C28#1 = 3: 47uF 63V, 6x12mm; ID: 3
C29 = 2: as C10 on sheet Microcontroller
R27#1 R29 = 15: ID: 15
R28#1 = RES-V-200K-250mW-THT
R30 = 15: 20K-100mW-±1%-0603; ID: 15
U4#1 = 1: Unipolar Motor Driver NMOS PWM 8-SO PowerPad; manufacturer: Texas Instrument; ID: 1

## Sheet SMPS.SchDoc
size A; SheetNumber: 5; SheetTotal: 6
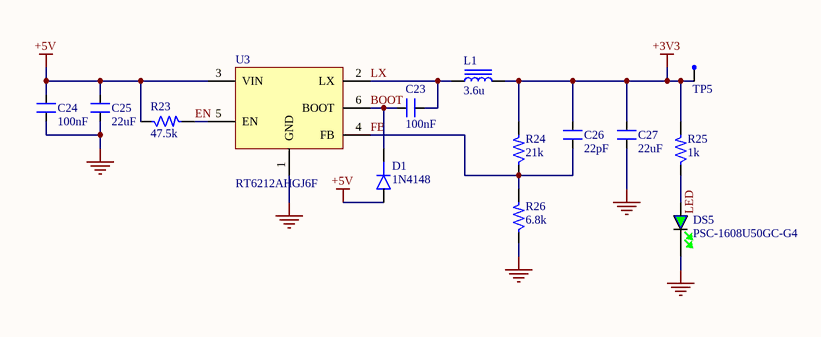
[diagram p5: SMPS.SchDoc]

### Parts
(Parts that share a designator on the sheet are numbered #1, #2 ... from top to bottom, then left to right.)
C23  100nF  [CAP-0603]
C24  100nF  [CAP-0603]
C25  22uF  [CAP-1206]
C26#1  22pF  [CAP-0603]
C27#1  22uF  [CAP-1206]
D1  1N4148  [Diode]
DS5#1  PSC-1608U50GC-G4  [LED_0603]
L1  3.6u  [IND_3.6uH]
R23  47.5k  [RES-0603]
R24#1  21k  [RES-1206]
R25#1  1k  [RES-0603]
R26#1  6.8k  [RES-1206]
TP5  Test-Point  [Test Point]  (value not drawn)
U3  RT6212AHGJ6F  [TSOT-23-6]

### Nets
+3V3: C26#1.1 C27#1.2 L1.2 R24#1.2 R25#1.2 TP5.1  [project net VDDA]
+5V: C24.2 C25.2 D1.A R23.1 U3.3(VIN)
GND: C24.1 C25.1 C27#1.1 DS5#1.K R26#1.1 U3.1(GND)
BOOT: C23.1 D1.K U3.6(BOOT)
EN: R23.2 U3.5(EN)
FB: C26#1.2 R24#1.1 R26#1.2 U3.4(FB)
LED: DS5#1.A R25#1.1
LX: C23.2 L1.1 U3.2(LX)

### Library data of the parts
C23 C24 = 2: as C10 on sheet Microcontroller
C25 C27#1 = 1: 25V 22uF X5R ±10% 1206 Multilayer Ceramic Capacitors MLCC - SMD/SMT ROHS; part number: GRM31CR61E226KE15L; manufacturer: Murata Electronics; ID: 1
C26#1 = 12: 50V 5%; ID: 12
D1 = N-1.5V-300mA-SOD123: 100V Independent Type 1.5V@300mA 4ns 300mA SOD-123 Switching Diodes ROHS; distr: LCSC; dpn: C84367
DS5#1 = LED_Green-3V-10mA-0603: as DS3 on sheet Buttons&Connectors
L1 = IND_3.6uH-4.9A-±30%-SMD: mfr: Taiyo Yuden; mpn: NRS8040T3R6NJGJ; pkg: SMD; distr: e-komponent; dpn: 587-2977-1-ND
R23 = 22: 47.5K-100mW-±1%-0603; ID: 22
R24#1 = 18: 21 kOhms ±1% 0.25W, 1/4W Chip Resistor 1206 (3216 Metric) Moisture Resistant Thick Film; part number: RC1206FR-0721KL; manufacturer: YAGEO; ID: 18
R25#1 = 16: as R1 on sheet Buttons&Connectors
R26#1 = 14: 6.8K-250mW-±5%-1206; ID: 14
U3 = 5: Step-down type Adjustable 2A 4.5V~18V 800mV~15.48V TSOT-23-6L DC-DC Converters ROHS; manufacturer: Richtek Tech; ID: 5

## Sheet TP4056.SchDoc
size C; SheetNumber: 6; SheetTotal: 6
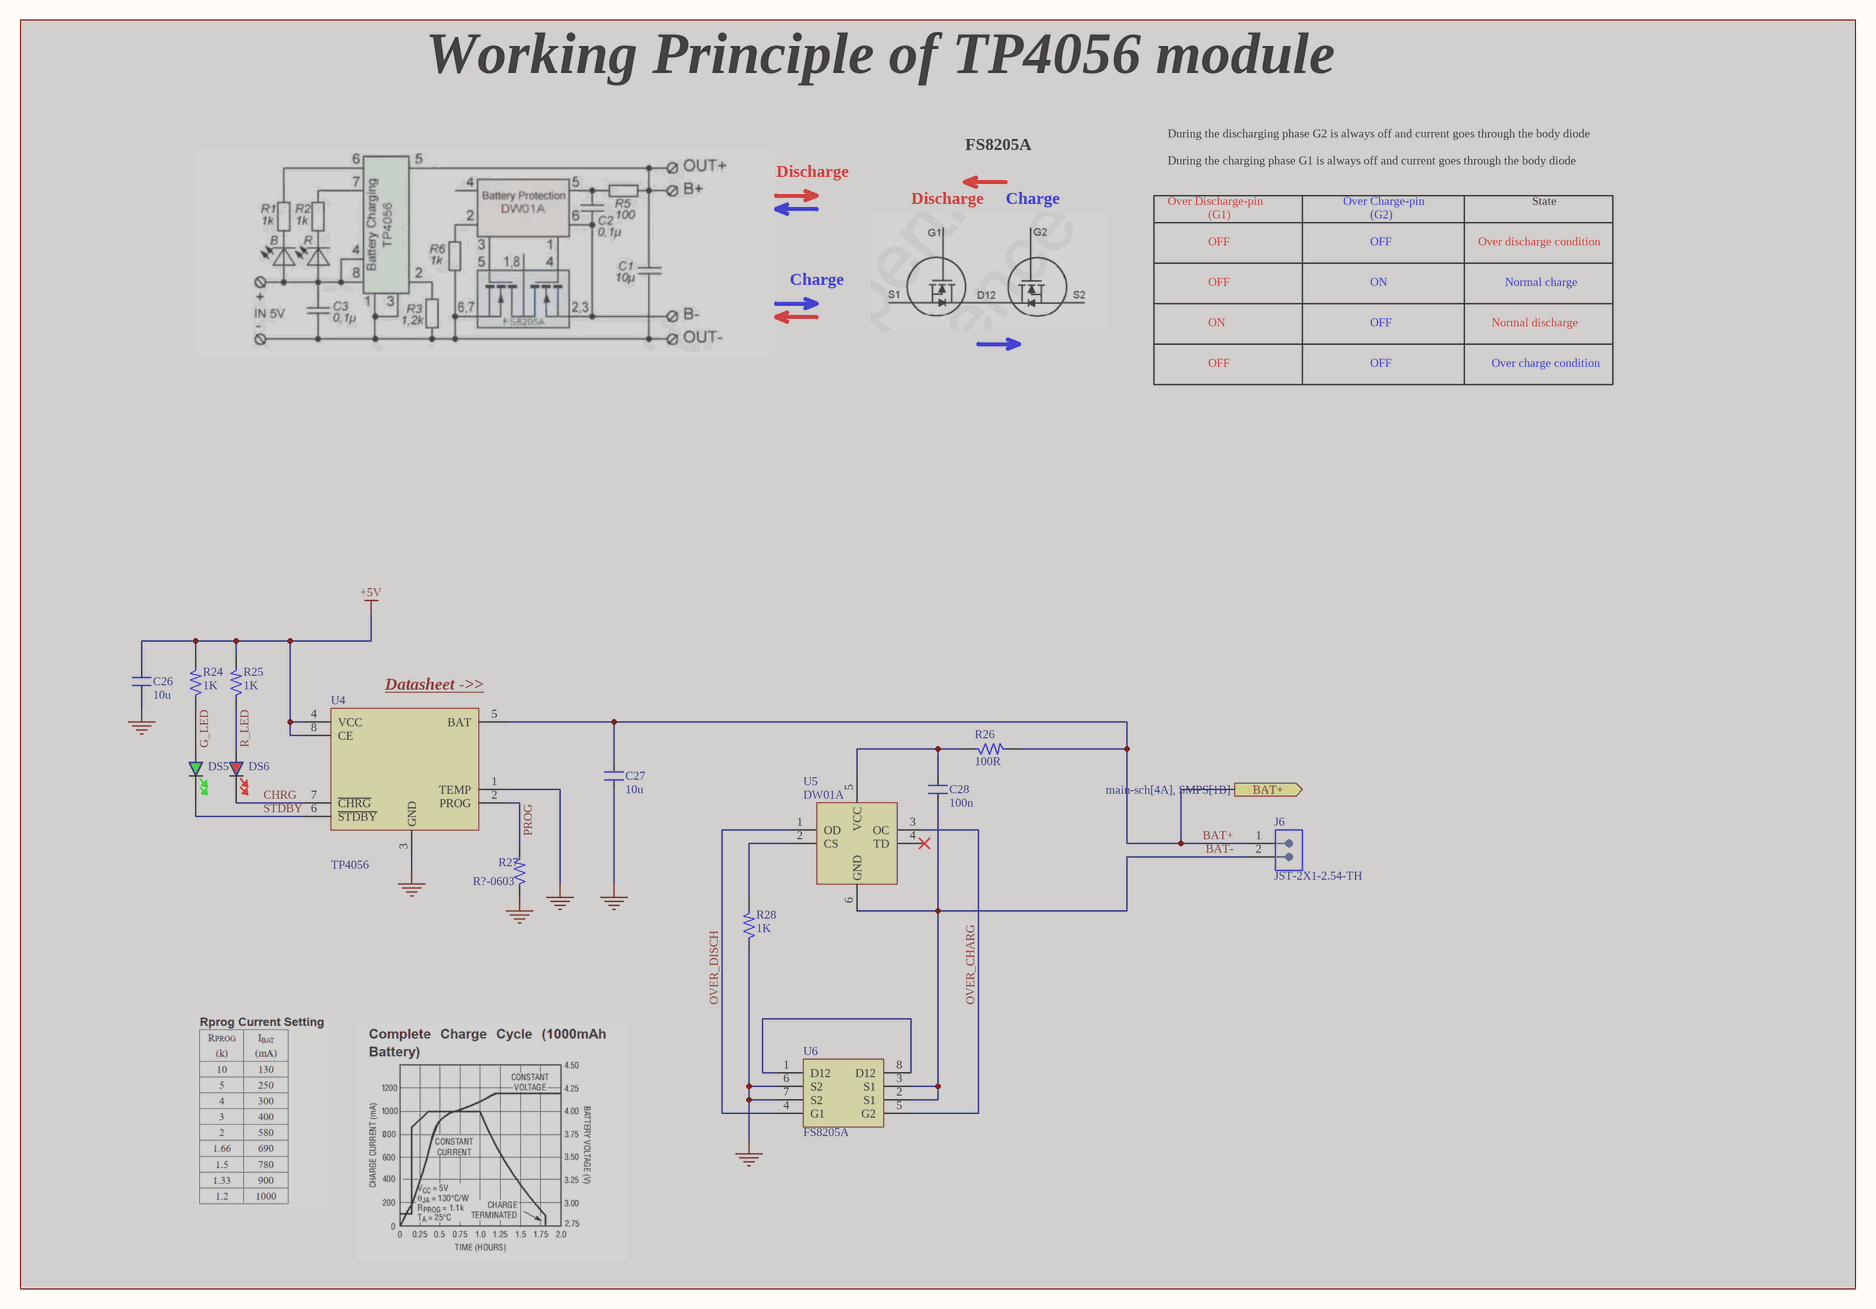
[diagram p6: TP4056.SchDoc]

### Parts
(Parts that share a designator on the sheet are numbered #1, #2 ... from top to bottom, then left to right.)
C26#2  10u  [CAP_0603]  (masked out: inside a compile mask, not in the netlist)
C27#2  10u  [CAP_0603]  (masked out: inside a compile mask, not in the netlist)
C28#2  100n  [CAP_0603]  (masked out: inside a compile mask, not in the netlist)
DS5#2  PSC-1608U50GC-G4  [LED_0603]  (value not drawn)  (masked out: inside a compile mask, not in the netlist)
DS6  NCD0603R6  [LED_0603]  (value not drawn)  (masked out: inside a compile mask, not in the netlist)
J6#2  JST-2X1-2.54-TH  (masked out: inside a compile mask, not in the netlist)
R24#2  1K  [RES_1206]  (masked out: inside a compile mask, not in the netlist)
R25#2  1K  [RES_1206]  (masked out: inside a compile mask, not in the netlist)
R26#2  100R  [RES_1206]  (masked out: inside a compile mask, not in the netlist)
R27#2  R?-0603  [RES_0603]  (masked out: inside a compile mask, not in the netlist)
R28#2  1K  [RES_1206]  (masked out: inside a compile mask, not in the netlist)
U4#2  TP4056  (masked out: inside a compile mask, not in the netlist)
U5  DW01A  (masked out: inside a compile mask, not in the netlist)
U6  FS8205A  (masked out: inside a compile mask, not in the netlist)

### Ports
BAT+ (out, see main-sch[4A], SMPS[1B])

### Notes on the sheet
- Working Principle of TP4056 module
- FS8205A
- During the discharging phase G2 is always off and current goes through the body diode
- During the charging phase G1 is always off and current goes through the body diode
- Discharge
- Charge
- Over Discharge-pin
- (G1)
- Over Charge-pin
- (G2)
- State
- OFF
- ON
- Over discharge condition
- Normal charge
- Over charge condition
- Normal discharge
- (near U4#2) Datasheet ->> <C:\UNIVERSITY\4.YIL\Bitirme Projesi\Datasheets\TP4056.pdf>

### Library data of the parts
C26#2 C27#2 = CAP-10uF-25V-±20%-0603: 25V 10uF X5R ±20% 0603; mfr: Samsung Electro-Mechanics; mpn: CL10A106MA8NRNC; pkg: 0603; distr: LCSC; dpn: C96446
C28#2 = CAP-100nF-25V-±10%-0603: 25V 100nF X7R ±10% 0603; mfr.: Samsung Electro-Mechanics; mpn: CL10B104KA8NNNC; pkg: 0603; distr.: LCSC; dpn: C1590
DS5#2 = LED_Green-3V-10mA-0603: Green 0603 LED Indication; mfr.: HONGLITRONIC; pkg: 0603; distr.: LCSC; dpn: C22371298
DS6 = LED_Red-2V-25mA-0603: 25mA Colorless Transparent Lens 30mcd~80mcd 620nm~630nm -30℃~+85℃ Red 140° 65mW 1.6V~2.4V 0603 LED Indication - Discrete ROHS; mfr.: Foshan NationStar Optoelectronics; pkg: 0603; distr.: LCSC; dpn: C7429910
R24#2 R25#2 R28#2 = RES-1K-250mW-±5-1206: pkg: 1206; distr: direnc; dpn: DSTK0018
R26#2 = RES-100R-250mW-±1-1206: mfr: yageo; mpn: RC1206FR-07100RL; pkg: 1206; distr: e-komponent; dpn: 311-100FRCT-ND
R27#2 = RES-R?-0603: pkg: 0603
U4#2 = TP4056: LION-BATTERY-CHARGER
U5 = DW01A: BATTERY-PROTECTION
U6 = FS8205A: n-mos

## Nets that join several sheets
+5V: Microcontroller (J6#1.27 J6#1.29), Buttons&Connectors (6 pins), SMPS (5 pins)
GND: Microcontroller (31 pins), Buttons&Connectors (26 pins), Motor-Driver (8 pins), SMPS (6 pins)
VDDA: Microcontroller (24 pins), Buttons&Connectors (12 pins), SMPS (6 pins)
BLUE_LED: Microcontroller (U2.81), Buttons&Connectors (R13.1)
BTN_1: Microcontroller (U2.95), Buttons&Connectors (C3.2 R5.1)
BTN_2: Microcontroller (U2.98), Buttons&Connectors (C4.2 R6.1)
BTN_3: Microcontroller (U2.97), Buttons&Connectors (C5.2 R16.1)
BTN_4: Microcontroller (U2.96), Buttons&Connectors (C6.2 R17.1)
GREEN_LED: Microcontroller (U2.77), Buttons&Connectors (R14.1)
LCD_I2C_SCL: Microcontroller (U2.92), Buttons&Connectors (J4.2)
LCD_I2C_SDA: Microcontroller (U2.93), Buttons&Connectors (J4.3)
LORA_AUX: Microcontroller (U2.24), Buttons&Connectors (J1.5)
LORA_M0: Microcontroller (U2.30), Buttons&Connectors (J1.1)
LORA_M1: Microcontroller (U2.29), Buttons&Connectors (J1.2)
LORA_RXD: Microcontroller (U2.25), Buttons&Connectors (J1.3)
LORA_TXD: Microcontroller (U2.26), Buttons&Connectors (J1.4)
MOTOR_CNT: Microcontroller (TP2.1 U2.35), Buttons&Connectors (C1.2 R4.2)
MOTOR_IN1: Microcontroller (TP3.1 U2.68), Motor-Driver (U4#1.3)
MOTOR_IN2: Microcontroller (TP4.1 U2.69), Motor-Driver (U4#1.2)
MOTOR_OUT1: Buttons&Connectors (J3.1), Motor-Driver (U4#1.6)
MOTOR_OUT2: Buttons&Connectors (J3.2), Motor-Driver (U4#1.8)
RED_LED: Microcontroller (U2.67), Buttons&Connectors (R15.1)
SDIO_CD: Microcontroller (U2.82), Buttons&Connectors (J5.9)
SDIO_CK: Microcontroller (U2.80), Buttons&Connectors (J5.5)
SDIO_CMD: Microcontroller (U2.83), Buttons&Connectors (J5.3)
SDIO_D1: Microcontroller (U2.66), Buttons&Connectors (J5.8 R8.1)
SDIO_D2: Microcontroller (U2.78), Buttons&Connectors (J5.1 R9.1)
SDIO_D3: Microcontroller (U2.79), Buttons&Connectors (J5.2 R10.1)
SDIO_DO: Microcontroller (U2.65), Buttons&Connectors (J5.7 R7.1)
USB_OTG_FS_N: Microcontroller (U2.70), Buttons&Connectors (U1.6)
USB_OTG_FS_P: Microcontroller (U2.71), Buttons&Connectors (U1.4)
